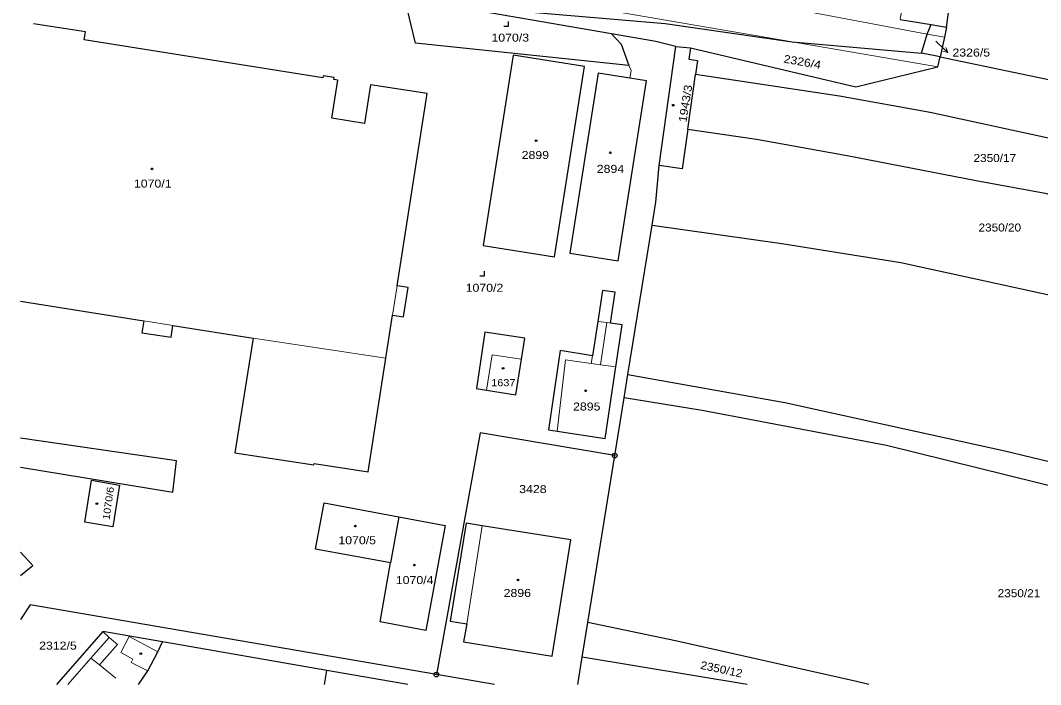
# Model space of a CAD drawing. Extents: x -652394 to -652006, y -1024262 to -1023975.
# Drawn here: x -652393.6 to -652176.9, y -1024262 to -1024121 of the extents above; entities that cross this region are included whole.
import ezdxf

# ---------------------------------------------------------------- set-up
doc = ezdxf.new("R2010")
doc.units = 0
doc.header["$LTSCALE"] = 0.46
doc.layers.add('63', color=7, linetype='Continuous', lineweight=25)

msp = doc.modelspace()

# ---------------------------------------------------------------- linework, layer by layer
at = {"layer": '63', "lineweight": 13}
for p, q in [((-652306.83, -1024112.26), (-652229.68, -1024125.5)), ((-652199.17, -1024125.4), (-652198.82, -1024125.73)), ((-652229.68, -1024125.5), (-652198.71, -1024130.81)), ((-652196.625, -1024127.777), (-652197.016, -1024126.727)), ((-652264.34, -1024130.52), (-652263.87, -1024131.58)), ((-652264.16, -1024133.23), (-652263.87, -1024131.58)), ((-652314.53, -1024183.57), (-652313.55, -1024177.33)), ((-652367.33, -1024184.75), (-652361.18, -1024185.73)), ((-652270.92, -1024184.88), (-652269.06, -1024185.14)), ((-652270.4, -1024194.1), (-652269.06, -1024185.14)), ((-652269.06, -1024185.14), (-652268.26, -1024185.26)), ((-652344.1, -1024188.47), (-652315.95, -1024192.69)), ((-652294.55, -1024199.5), (-652293.38, -1024191.96)), ((-652293.38, -1024191.96), (-652287.16, -1024192.92)), ((-652272.32, -1024193.84), (-652272.06, -1024192.18)), ((-652279.57, -1024208.2), (-652277.8, -1024193.03)), ((-652277.8, -1024193.03), (-652272.32, -1024193.84)), ((-652272.32, -1024193.84), (-652270.4, -1024194.1)), ((-652270.4, -1024194.1), (-652267.1, -1024194.56)), ((-652295.52, -1024228.28), (-652298.75, -1024249.1)), ((-652376.07, -1024250.77), (-652374.69, -1024252.01)), ((-652378.57, -1024256.44), (-652374.69, -1024252.01)), ((-652374.69, -1024252.01), (-652372.97, -1024253.54)), ((-652376.73, -1024257.85), (-652372.97, -1024253.54)), ((-652372.23, -1024255.19), (-652369.67, -1024256.65)), ((-652383.463, -1024262.022), (-652378.57, -1024256.44)), ((-652378.57, -1024256.44), (-652376.73, -1024257.85)), ((-652370.04, -1024257.3), (-652369.67, -1024256.65)), ((-652370.04, -1024257.3), (-652366.48, -1024259.11)), ((-652376.73, -1024257.85), (-652373.26, -1024260.68))]:
    msp.add_line(p, q, dxfattribs=at)
at = {"layer": '63'}
for p, q in [((-652196.89, -1024122.39), (-652196.06, -1024116.16)), ((-652268.06, -1024123.78), (-652304.24, -1024117.59)), ((-652206.77, -1024120.74), (-652200.18, -1024121.84)), ((-652200.18, -1024121.84), (-652196.89, -1024122.39)), ((-652268.06, -1024123.78), (-652265.96, -1024125.99)), ((-652265.96, -1024125.99), (-652264.34, -1024130.52)), ((-652257.95, -1024151.77), (-652254.37, -1024126.49)), ((-652254.37, -1024126.49), (-652251.28, -1024126.81)), ((-652198.26, -1024128.72), (-652202.22, -1024127.9)), ((-652251.83, -1024144.08), (-652250.2, -1024132.43)), ((-652251.83, -1024144.08), (-652253.01, -1024152.48)), ((-652258.61, -1024159.53), (-652257.95, -1024151.77)), ((-652253.01, -1024152.48), (-652257.95, -1024151.77)), ((-652259.41, -1024164.46), (-652258.61, -1024159.53)), ((-652267.35, -1024213.4), (-652265.35, -1024201.09)), ((-652273.09, -1024248.8), (-652267.35, -1024213.4)), ((-652313.17, -1024226.37), (-652314.97, -1024236.19)), ((-652274.29, -1024256.23), (-652273.09, -1024248.8)), ((-652328.51, -1024259), (-652363.39, -1024252.96)), ((-652275.217, -1024262.022), (-652274.29, -1024256.23)), ((-652239.201, -1024262.022), (-652274.29, -1024256.23)), ((-652328.979, -1024262.022), (-652328.51, -1024259)), ((-652311.274, -1024262.022), (-652328.51, -1024259)), ((-652292.871, -1024262.022), (-652305.22, -1024259.9))]:
    msp.add_line(p, q, dxfattribs=at)
at = {"layer": '63', "lineweight": 13}
for points in [[(-652196.89, -1024122.39), (-652196.06, -1024116.16), (-652195.63, -1024112.89), (-652195.04, -1024112.97), (-652193.37, -1024103.11), (-652222.47, -1024098.26), (-652224.11, -1024108.14), (-652205.17, -1024111.28), (-652206.77, -1024120.74), (-652200.18, -1024121.84)], [(-652224.11, -1024108.14), (-652205.17, -1024111.28), (-652206.77, -1024120.74), (-652200.18, -1024121.84), (-652196.89, -1024122.39), (-652196.06, -1024116.16), (-652195.63, -1024112.89), (-652195.04, -1024112.97), (-652193.37, -1024103.11), (-652222.47, -1024098.26)], [(-652268.06, -1024123.78), (-652304.24, -1024117.59), (-652305.77, -1024117.34), (-652311.91, -1024116.32), (-652309.68, -1024125.83), (-652264.34, -1024130.52), (-652265.96, -1024125.99)], [(-652251.28, -1024126.81), (-652216.19, -1024135.06), (-652198.71, -1024130.81), (-652198.26, -1024128.72), (-652202.22, -1024127.9), (-652229.68, -1024125.5), (-652256.65, -1024121.65), (-652304.24, -1024117.59), (-652268.06, -1024123.78), (-652258.59, -1024125.42), (-652254.37, -1024126.49)], [(-652196.89, -1024122.39), (-652200.18, -1024121.84), (-652201.01, -1024123.89), (-652202.22, -1024127.9), (-652198.26, -1024128.72), (-652197.36, -1024124.55)], [(-652250.2, -1024132.43), (-652249.79, -1024129.48), (-652251.61, -1024129.17), (-652251.28, -1024126.81), (-652254.37, -1024126.49), (-652257.95, -1024151.77), (-652253.01, -1024152.48), (-652251.83, -1024144.08)], [(-652251.61, -1024129.17), (-652251.28, -1024126.81), (-652254.37, -1024126.49), (-652257.95, -1024151.77), (-652253.01, -1024152.48), (-652251.83, -1024144.08), (-652250.2, -1024132.43), (-652249.79, -1024129.48)], [(-652273.75, -1024130.73), (-652288.94, -1024128.34), (-652295.27, -1024168.75), (-652280.12, -1024171.18)], [(-652295.27, -1024168.75), (-652280.12, -1024171.18), (-652273.75, -1024130.73), (-652288.94, -1024128.34)], [(-652260.57, -1024133.79), (-652264.16, -1024133.23), (-652270.84, -1024132.18), (-652276.86, -1024170.41), (-652266.61, -1024172.02)], [(-652276.86, -1024170.41), (-652266.61, -1024172.02), (-652260.57, -1024133.79), (-652264.16, -1024133.23), (-652270.84, -1024132.18)], [(-652122.53, -1024162.65), (-652122.69, -1024155.4), (-652145.34, -1024151.05), (-652173.97, -1024146.26), (-652200.37, -1024140.5), (-652219.59, -1024137.03), (-652250.2, -1024132.43), (-652251.83, -1024144.08), (-652237.23, -1024146.17), (-652218.01, -1024149.63), (-652190.61, -1024154.99), (-652175.94, -1024157.67), (-652175.43, -1024157.76), (-652164.78, -1024159.71), (-652147.99, -1024163.59), (-652147.5, -1024163.71), (-652137.65, -1024165.98), (-652127.22, -1024168.72), (-652126.12, -1024162.11)], [(-652251.83, -1024144.08), (-652253.01, -1024152.48), (-652257.95, -1024151.77), (-652258.61, -1024159.53), (-652259.41, -1024164.46), (-652231.87, -1024168.37), (-652206.61, -1024172.41), (-652170.95, -1024180.16), (-652130.83, -1024190.46), (-652127.39, -1024169.76), (-652127.22, -1024168.72), (-652137.65, -1024165.98), (-652147.5, -1024163.71), (-652147.99, -1024163.59), (-652164.78, -1024159.71), (-652175.43, -1024157.76), (-652175.94, -1024157.67), (-652190.61, -1024154.99), (-652218.01, -1024149.63), (-652237.23, -1024146.17)], [(-652265.77, -1024185.63), (-652268.26, -1024185.26), (-652267.28, -1024178.7), (-652269.96, -1024178.29), (-652270.92, -1024184.88), (-652272.06, -1024192.18), (-652278.94, -1024191.1), (-652281.41, -1024207.92), (-652279.57, -1024208.2), (-652269.37, -1024209.76), (-652267.1, -1024194.56)], [(-652286.47, -1024188.48), (-652294.92, -1024187.16), (-652296.72, -1024199.15), (-652294.55, -1024199.5), (-652288.33, -1024200.5), (-652287.16, -1024192.92)], [(-652294.55, -1024199.5), (-652288.33, -1024200.5), (-652287.16, -1024192.92), (-652293.38, -1024191.96)], [(-652279.57, -1024208.2), (-652269.37, -1024209.76), (-652267.1, -1024194.56), (-652270.4, -1024194.1), (-652272.32, -1024193.84), (-652277.8, -1024193.03)], [(-652378.49, -1024218.64), (-652379.86, -1024227.54), (-652373.91, -1024228.49), (-652372.5, -1024219.66)], [(-652379.86, -1024227.54), (-652373.91, -1024228.49), (-652372.5, -1024219.66), (-652378.49, -1024218.64)], [(-652313.17, -1024226.37), (-652329.05, -1024223.45), (-652330.88, -1024233.25), (-652314.97, -1024236.19)], [(-652330.88, -1024233.25), (-652314.97, -1024236.19), (-652313.17, -1024226.37), (-652329.05, -1024223.45)], [(-652313.17, -1024226.37), (-652314.97, -1024236.19), (-652317.18, -1024248.72), (-652307.43, -1024250.52), (-652303.38, -1024228.23)], [(-652317.18, -1024248.72), (-652307.43, -1024250.52), (-652303.38, -1024228.23), (-652313.17, -1024226.37), (-652314.97, -1024236.19)], [(-652280.63, -1024255.98), (-652276.64, -1024231.28), (-652295.52, -1024228.28), (-652298.93, -1024227.72), (-652302.27, -1024248.53), (-652298.75, -1024249.1), (-652299.48, -1024252.93)], [(-652295.52, -1024228.28), (-652298.75, -1024249.1), (-652299.48, -1024252.93), (-652280.63, -1024255.98), (-652276.64, -1024231.28)]]:
    msp.add_lwpolyline(points, close=True, dxfattribs=at)
at = {"layer": '63'}
for points in [[(-652264.34, -1024130.52), (-652309.68, -1024125.83), (-652311.91, -1024116.32)], [(-652304.24, -1024117.59), (-652256.65, -1024121.65), (-652229.68, -1024125.5), (-652202.22, -1024127.9)], [(-652327.45, -1024141.75), (-652326.16, -1024133.63), (-652327.01, -1024133.5), (-652326.95, -1024133.1), (-652329.27, -1024132.73), (-652329.33, -1024133.13), (-652380.02, -1024125.11), (-652379.75, -1024123.41), (-652390.79, -1024121.71)], [(-652290.881, -1024122.18), (-652289.88, -1024122.18), (-652289.88, -1024121.18)], [(-652202.22, -1024127.9), (-652201.01, -1024123.89), (-652200.18, -1024121.84)], [(-652196.89, -1024122.39), (-652197.36, -1024124.55), (-652198.26, -1024128.72)], [(-652254.37, -1024126.49), (-652258.59, -1024125.42), (-652268.06, -1024123.78)], [(-652251.28, -1024126.81), (-652251.61, -1024129.17), (-652249.79, -1024129.48), (-652250.2, -1024132.43)], [(-652251.28, -1024126.81), (-652216.19, -1024135.06), (-652198.71, -1024130.81), (-652198.26, -1024128.72)], [(-652198.26, -1024128.72), (-652174.89, -1024133.55), (-652133.42, -1024140.71), (-652109.38, -1024144.99), (-652070.02, -1024157.71), (-652064.99, -1024159.32), (-652012.85, -1024174.11)], [(-652173.97, -1024146.26), (-652200.37, -1024140.5), (-652219.59, -1024137.03), (-652250.2, -1024132.43)], [(-652393.553, -1024180.573), (-652367.33, -1024184.75), (-652367.74, -1024187.32), (-652361.57, -1024188.24), (-652361.18, -1024185.73), (-652344.1, -1024188.47), (-652348.02, -1024212.81), (-652331.22, -1024215.38), (-652331.17, -1024215.07), (-652319.71, -1024216.82), (-652315.95, -1024192.69), (-652314.53, -1024183.57), (-652312.23, -1024183.93), (-652311.23, -1024177.69), (-652313.55, -1024177.33), (-652307.18, -1024136.46), (-652319.21, -1024134.61), (-652320.51, -1024142.85), (-652327.45, -1024141.75)], [(-652251.83, -1024144.08), (-652237.23, -1024146.17), (-652218.01, -1024149.63), (-652190.61, -1024154.99), (-652175.94, -1024157.67), (-652175.43, -1024157.76), (-652164.78, -1024159.71), (-652147.99, -1024163.59), (-652147.5, -1024163.71), (-652137.65, -1024165.98), (-652127.22, -1024168.72)], [(-652265.35, -1024201.09), (-652264.55, -1024196.15), (-652259.41, -1024164.46)], [(-652259.41, -1024164.46), (-652231.87, -1024168.37), (-652206.61, -1024172.41), (-652170.95, -1024180.16), (-652130.83, -1024190.46), (-652133.34, -1024205.54)], [(-652295.981, -1024175.24), (-652294.98, -1024175.24), (-652294.98, -1024174.24)], [(-652264.55, -1024196.15), (-652231.24, -1024202.08), (-652184.5, -1024212.41), (-652134.85, -1024224.32), (-652097.87, -1024233.14), (-652065.32, -1024241.16)], [(-652101.939, -1024262.022), (-652096.17, -1024240.13), (-652144.74, -1024227.85), (-652171.01, -1024220.79), (-652209.63, -1024211.21), (-652248.76, -1024203.78), (-652265.35, -1024201.09)], [(-652393.553, -1024215.872), (-652361.19, -1024221.12), (-652360.43, -1024214.51), (-652393.553, -1024209.688)], [(-652267.35, -1024213.4), (-652295.94, -1024208.58), (-652305.22, -1024259.9)], [(-652314.97, -1024236.19), (-652330.88, -1024233.25), (-652329.05, -1024223.45), (-652313.17, -1024226.37)], [(-652313.17, -1024226.37), (-652303.38, -1024228.23), (-652307.43, -1024250.52), (-652317.18, -1024248.72), (-652314.97, -1024236.19)], [(-652393.553, -1024238.864), (-652390.93, -1024236.73), (-652393.553, -1024233.882)], [(-652305.22, -1024259.9), (-652391.46, -1024245.11), (-652393.553, -1024248.174)], [(-652213.387, -1024262.022), (-652216, -1024261.36), (-652254.43, -1024252.73), (-652273.09, -1024248.8)], [(-652363.39, -1024252.96), (-652376.07, -1024250.77), (-652385.885, -1024262.022)], [(-652368.444, -1024262.022), (-652366.48, -1024259.11), (-652364.34, -1024255.08), (-652363.39, -1024252.96)]]:
    msp.add_lwpolyline(points, dxfattribs=at)
at = {"layer": '63', "lineweight": 13}
for points in [[(-652304.24, -1024117.59), (-652256.65, -1024121.65), (-652229.68, -1024125.5), (-652202.22, -1024127.9), (-652201.01, -1024123.89), (-652200.18, -1024121.84), (-652206.77, -1024120.74)], [(-652234.43, -1024117.59), (-652201.01, -1024123.89), (-652197.36, -1024124.55)], [(-652174.89, -1024133.55), (-652198.26, -1024128.72), (-652198.71, -1024130.81), (-652216.19, -1024135.06), (-652251.28, -1024126.81), (-652251.61, -1024129.17), (-652249.79, -1024129.48), (-652250.2, -1024132.43), (-652219.59, -1024137.03), (-652200.37, -1024140.5), (-652173.97, -1024146.26)], [(-652198.82, -1024125.73), (-652196.625, -1024127.777), (-652197.699, -1024127.46)], [(-652170.95, -1024180.16), (-652206.61, -1024172.41), (-652231.87, -1024168.37), (-652259.41, -1024164.46), (-652264.55, -1024196.15), (-652231.24, -1024202.08), (-652184.5, -1024212.41), (-652134.85, -1024224.32)], [(-652372.23, -1024255.19), (-652370.45, -1024251.82), (-652364.34, -1024255.08)]]:
    msp.add_lwpolyline(points, dxfattribs=at)
at = {"layer": '63'}
for points in [[(-652273.75, -1024130.73), (-652288.94, -1024128.34), (-652295.27, -1024168.75), (-652280.12, -1024171.18)], [(-652260.57, -1024133.79), (-652264.16, -1024133.23), (-652270.84, -1024132.18), (-652276.86, -1024170.41), (-652266.61, -1024172.02)], [(-652265.77, -1024185.63), (-652268.26, -1024185.26), (-652267.28, -1024178.7), (-652269.96, -1024178.29), (-652270.92, -1024184.88), (-652272.06, -1024192.18), (-652278.94, -1024191.1), (-652281.41, -1024207.92), (-652279.57, -1024208.2), (-652269.37, -1024209.76), (-652267.1, -1024194.56)], [(-652286.47, -1024188.48), (-652294.92, -1024187.16), (-652296.72, -1024199.15), (-652294.55, -1024199.5), (-652288.33, -1024200.5), (-652287.16, -1024192.92)], [(-652378.49, -1024218.64), (-652372.5, -1024219.66), (-652373.91, -1024228.49), (-652379.86, -1024227.54)], [(-652280.63, -1024255.98), (-652276.64, -1024231.28), (-652295.52, -1024228.28), (-652298.93, -1024227.72), (-652302.27, -1024248.53), (-652298.75, -1024249.1), (-652299.48, -1024252.93)]]:
    msp.add_lwpolyline(points, close=True, dxfattribs=at)
for centre, radius in [((-652254.9368, -1024138.9792), 0.175), ((-652284.0468, -1024146.5192), 0.175), ((-652268.2868, -1024149.0692), 0.175), ((-652365.5968, -1024152.4992), 0.175), ((-652291.0568, -1024194.8592), 0.175), ((-652273.5168, -1024199.6192), 0.175), ((-652267.35, -1024213.3999), 0.5), ((-652267.35, -1024213.3999), 0.0303), ((-652377.3168, -1024223.6092), 0.175), ((-652322.4168, -1024228.3692), 0.175), ((-652309.9168, -1024236.6492), 0.175), ((-652287.8968, -1024239.7992), 0.175), ((-652367.9868, -1024255.4392), 0.175), ((-652305.22, -1024259.8999), 0.5), ((-652305.22, -1024259.8999), 0.0303)]:
    msp.add_circle(centre, radius, dxfattribs=at)

# ---------------------------------------------------------------- texts
for s, height, width, p in [('1070/3', 1.7, 1.15, (-652293.535, -1024125.47)), ('2326/5', 1.7, 1.15, (-652195.64, -1024128.64)), ('2899', 1.7, 1.15, (-652287.117, -1024150.4)), ('2350/17', 1.7, 1.1, (-652191.16, -1024151.03)), ('2894', 1.7, 1.15, (-652271.167, -1024153.34)), ('1070/1', 1.7, 1.15, (-652369.445, -1024156.47)), ('2350/20', 1.7, 1.1, (-652190.1, -1024165.8)), ('1070/2', 1.7, 1.15, (-652299.005, -1024178.59)), ('1637', 1.5, 1.15, (-652293.572, -1024198.65)), ('2895', 1.7, 1.15, (-652276.197, -1024203.81)), ('3428', 1.7, 1.15, (-652287.637, -1024221.35)), ('1070/5', 1.7, 1.15, (-652326.035, -1024232.22)), ('1070/4', 1.7, 1.15, (-652313.835, -1024240.67)), ('2896', 1.7, 1.15, (-652290.947, -1024243.41)), ('2350/21', 1.7, 1.1, (-652186.03, -1024243.46)), ('2312/5', 1.7, 1.15, (-652389.575, -1024254.59))]:
    msp.add_text(s, height=height, dxfattribs=dict(at, width=width)).set_placement(p)
for s, height, rotation, width, p in [('2326/4', 1.7, 350, 1.15, (-652231.597, -1024129.907)), ('1943/3', 1.7, 81, 1.15, (-652252.13, -1024142.692)), ('1070/6', 1.5, 82, 1.15, (-652374.633, -1024227.112)), ('2350/12', 1.7, 348, 1.1, (-652249.276, -1024258.651))]:
    msp.add_text(s, height=height, rotation=rotation, dxfattribs=dict(at, width=width)).set_placement(p)

doc.saveas('drawing.dxf')
